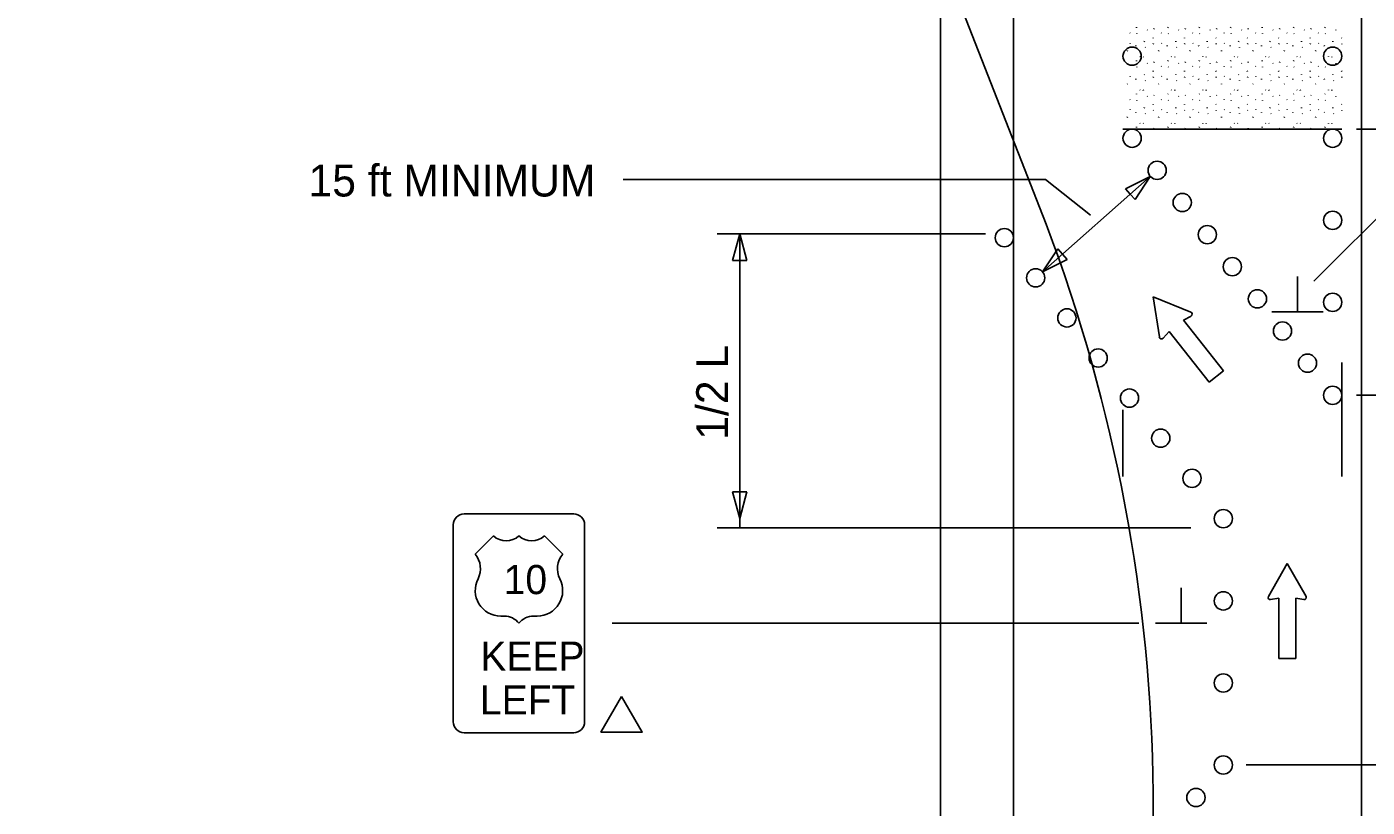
# Model space of a CAD drawing. Extents: x 16486 to 19505, y 5576 to 6998.
# Drawn here: x 16688.1 to 16981.9, y 6297.8 to 6469 of the extents above; entities that cross this region are included whole.
import ezdxf

# ---------------------------------------------------------------- set-up
doc = ezdxf.new("R2010")
doc.units = 0
for name, color, linetype in [('ALI_LEGAL_EX', 7, 'Continuous'), ('MT_SCRATCH_LEVEL_A', 7, 'Continuous'), ('MT_SCRATCH_LEVEL_E', 7, 'Continuous'), ('PAVT_EDGE_EX', 7, 'Continuous'), ('TRAFFIC_SIGNS_PR', 7, 'Continuous'), ('TYPICAL_EX', 7, 'Continuous'), ('TYPICAL_TEXT_DIMEN_PR', 7, 'Continuous')]:
    doc.layers.add(name, color=color, linetype=linetype)

msp = doc.modelspace()

# ---------------------------------------------------------------- linework, layer by layer
at = {"layer": 'ALI_LEGAL_EX'}
for p, q in [((16688.08, 6997.81), (16910.11, 6429.44)), ((16980.68, 6974.12), (16980.68, 6155.98)), ((16980.68, 6922.21), (16980.68, 6058.3))]:
    msp.add_line(p, q, dxfattribs=at)
for points in [[(16976.4, 6370.33), (16976.4, 6395.33)], [(16928.4, 6370.33), (16928.4, 6384.97)]]:
    msp.add_lwpolyline(points, dxfattribs=at)
msp.add_arc((16571.06, 6296.99), 364, 341.1474, 21.3382, dxfattribs=at)
at = {"layer": 'MT_SCRATCH_LEVEL_A'}
for p, q in [((16931.35, 6468.75), (16931.4, 6468.87)), ((16933.72, 6468.3), (16933.77, 6468.23)), ((16935.17, 6468.45), (16935.22, 6468.57)), ((16938.24, 6468.75), (16938.29, 6468.87)), ((16940.6, 6468.3), (16940.66, 6468.23)), ((16942.05, 6468.45), (16942.1, 6468.57)), ((16945.12, 6468.75), (16945.17, 6468.87)), ((16947.49, 6468.3), (16947.54, 6468.23)), ((16948.94, 6468.45), (16948.99, 6468.57)), ((16952.01, 6468.75), (16952.06, 6468.87)), ((16954.38, 6468.3), (16954.43, 6468.23)), ((16955.83, 6468.45), (16955.88, 6468.57)), ((16958.9, 6468.75), (16958.95, 6468.87)), ((16961.27, 6468.3), (16961.32, 6468.23)), ((16962.72, 6468.45), (16962.77, 6468.57)), ((16965.78, 6468.75), (16965.84, 6468.87)), ((16968.15, 6468.3), (16968.21, 6468.23)), ((16969.6, 6468.45), (16969.65, 6468.57)), ((16972.67, 6468.75), (16972.72, 6468.87)), ((16975.04, 6468.3), (16975.09, 6468.23)), ((16929.9, 6467.62), (16929.95, 6467.55)), ((16929.95, 6465.42), (16930, 6465.34)), ((16931.43, 6467.49), (16931.48, 6467.41)), ((16933.07, 6465.7), (16933.12, 6465.81)), ((16934.99, 6466.57), (16935.05, 6466.49)), ((16935.04, 6465.16), (16935.09, 6465.28)), ((16936.78, 6467.62), (16936.84, 6467.55)), ((16936.83, 6465.42), (16936.89, 6465.34)), ((16938.31, 6467.49), (16938.37, 6467.41)), ((16939.96, 6465.7), (16940.01, 6465.81)), ((16941.88, 6466.57), (16941.93, 6466.49)), ((16941.92, 6465.16), (16941.98, 6465.28)), ((16943.67, 6467.62), (16943.72, 6467.55)), ((16943.72, 6465.42), (16943.77, 6465.34)), ((16945.2, 6467.49), (16945.25, 6467.41)), ((16946.84, 6465.7), (16946.9, 6465.81)), ((16948.77, 6466.57), (16948.82, 6466.49)), ((16948.81, 6465.16), (16948.86, 6465.28)), ((16950.56, 6467.62), (16950.61, 6467.55)), ((16950.61, 6465.42), (16950.66, 6465.34)), ((16952.09, 6467.49), (16952.14, 6467.41)), ((16953.73, 6465.7), (16953.78, 6465.81)), ((16955.66, 6466.57), (16955.71, 6466.49)), ((16955.7, 6465.16), (16955.75, 6465.28)), ((16957.45, 6467.62), (16957.5, 6467.55)), ((16957.5, 6465.42), (16957.55, 6465.34)), ((16958.98, 6467.49), (16959.03, 6467.41)), ((16960.62, 6465.7), (16960.67, 6465.81)), ((16962.54, 6466.57), (16962.6, 6466.49)), ((16962.59, 6465.16), (16962.64, 6465.28)), ((16964.33, 6467.62), (16964.39, 6467.55)), ((16964.38, 6465.42), (16964.44, 6465.34)), ((16965.87, 6467.49), (16965.92, 6467.41)), ((16967.51, 6465.7), (16967.56, 6465.81)), ((16969.43, 6466.57), (16969.48, 6466.49)), ((16969.47, 6465.16), (16969.53, 6465.28)), ((16971.22, 6467.62), (16971.27, 6467.55)), ((16971.27, 6465.42), (16971.32, 6465.34)), ((16972.75, 6467.49), (16972.8, 6467.41)), ((16974.39, 6465.7), (16974.45, 6465.81)), ((16976.32, 6466.57), (16976.37, 6466.49)), ((16976.36, 6465.16), (16976.4, 6465.25)), ((16929.33, 6463.66), (16929.38, 6463.78)), ((16931.23, 6464.84), (16931.24, 6464.72)), ((16932.11, 6462.43), (16932.16, 6462.35)), ((16932.85, 6462.4), (16932.9, 6462.32)), ((16933.26, 6464.5), (16933.31, 6464.42)), ((16936.22, 6463.66), (16936.27, 6463.78)), ((16938.12, 6464.84), (16938.13, 6464.72)), ((16939, 6462.43), (16939.05, 6462.35)), ((16939.74, 6462.4), (16939.79, 6462.32)), ((16940.15, 6464.5), (16940.2, 6464.42)), ((16943.1, 6463.66), (16943.15, 6463.78)), ((16945, 6464.84), (16945.01, 6464.72)), ((16945.89, 6462.43), (16945.94, 6462.35)), ((16946.62, 6462.4), (16946.67, 6462.32)), ((16947.03, 6464.5), (16947.08, 6464.42)), ((16949.99, 6463.66), (16950.04, 6463.78)), ((16951.89, 6464.84), (16951.9, 6464.72)), ((16952.77, 6462.43), (16952.83, 6462.35)), ((16953.51, 6462.4), (16953.56, 6462.32)), ((16953.92, 6464.5), (16953.97, 6464.42)), ((16956.88, 6463.66), (16956.93, 6463.78)), ((16958.78, 6464.84), (16958.79, 6464.72)), ((16959.66, 6462.43), (16959.71, 6462.35)), ((16960.4, 6462.4), (16960.45, 6462.32)), ((16960.81, 6464.5), (16960.86, 6464.42)), ((16963.76, 6463.66), (16963.82, 6463.78)), ((16965.67, 6464.84), (16965.68, 6464.72)), ((16966.55, 6462.43), (16966.6, 6462.35)), ((16967.29, 6462.4), (16967.34, 6462.32)), ((16967.69, 6464.5), (16967.75, 6464.42)), ((16970.65, 6463.66), (16970.7, 6463.78)), ((16972.55, 6464.84), (16972.56, 6464.72)), ((16973.44, 6462.43), (16973.49, 6462.35)), ((16974.17, 6462.4), (16974.22, 6462.32)), ((16974.58, 6464.5), (16974.63, 6464.42)), ((16931.35, 6461.47), (16931.4, 6461.58)), ((16931.43, 6460.2), (16931.48, 6460.12)), ((16933.72, 6461.02), (16933.77, 6460.94)), ((16935.17, 6461.17), (16935.22, 6461.28)), ((16936.78, 6460.34), (16936.84, 6460.26)), ((16938.24, 6461.47), (16938.29, 6461.58)), ((16938.31, 6460.2), (16938.37, 6460.12)), ((16940.6, 6461.02), (16940.66, 6460.94)), ((16942.05, 6461.17), (16942.1, 6461.28)), ((16943.67, 6460.34), (16943.72, 6460.26)), ((16945.12, 6461.47), (16945.17, 6461.58)), ((16945.2, 6460.2), (16945.25, 6460.12)), ((16947.49, 6461.02), (16947.54, 6460.94)), ((16948.94, 6461.17), (16948.99, 6461.28)), ((16950.56, 6460.34), (16950.61, 6460.26)), ((16952.01, 6461.47), (16952.06, 6461.58)), ((16952.09, 6460.2), (16952.14, 6460.12)), ((16954.38, 6461.02), (16954.43, 6460.94)), ((16955.83, 6461.17), (16955.88, 6461.28)), ((16957.45, 6460.34), (16957.5, 6460.26)), ((16958.9, 6461.47), (16958.95, 6461.58)), ((16958.98, 6460.2), (16959.03, 6460.12)), ((16961.27, 6461.02), (16961.32, 6460.94)), ((16962.72, 6461.17), (16962.77, 6461.28)), ((16964.33, 6460.34), (16964.39, 6460.26)), ((16965.78, 6461.47), (16965.84, 6461.58)), ((16965.87, 6460.2), (16965.92, 6460.12)), ((16968.15, 6461.02), (16968.21, 6460.94)), ((16969.6, 6461.17), (16969.65, 6461.28)), ((16971.22, 6460.34), (16971.27, 6460.26)), ((16972.67, 6461.47), (16972.72, 6461.58)), ((16972.75, 6460.2), (16972.8, 6460.12)), ((16975.04, 6461.02), (16975.09, 6460.94)), ((16929.33, 6456.38), (16929.38, 6456.49)), ((16929.95, 6458.13), (16930, 6458.05)), ((16931.23, 6457.56), (16931.24, 6457.44)), ((16933.07, 6458.41), (16933.12, 6458.53)), ((16933.26, 6457.21), (16933.31, 6457.13)), ((16934.99, 6459.28), (16935.05, 6459.2)), ((16935.04, 6457.88), (16935.09, 6458)), ((16936.22, 6456.38), (16936.27, 6456.49)), ((16936.83, 6458.13), (16936.89, 6458.05)), ((16938.12, 6457.56), (16938.13, 6457.44)), ((16939.96, 6458.41), (16940.01, 6458.53)), ((16940.15, 6457.21), (16940.2, 6457.13)), ((16941.88, 6459.28), (16941.93, 6459.2)), ((16941.92, 6457.88), (16941.98, 6458)), ((16943.1, 6456.38), (16943.15, 6456.49)), ((16943.72, 6458.13), (16943.77, 6458.05)), ((16945, 6457.56), (16945.01, 6457.44)), ((16946.84, 6458.41), (16946.9, 6458.53)), ((16947.03, 6457.21), (16947.08, 6457.13)), ((16948.77, 6459.28), (16948.82, 6459.2)), ((16948.81, 6457.88), (16948.86, 6458)), ((16949.99, 6456.38), (16950.04, 6456.49)), ((16950.61, 6458.13), (16950.66, 6458.05)), ((16951.89, 6457.56), (16951.9, 6457.44)), ((16953.73, 6458.41), (16953.78, 6458.53)), ((16953.92, 6457.21), (16953.97, 6457.13)), ((16955.66, 6459.28), (16955.71, 6459.2)), ((16955.7, 6457.88), (16955.75, 6458)), ((16956.88, 6456.38), (16956.93, 6456.49)), ((16957.5, 6458.13), (16957.55, 6458.05)), ((16958.78, 6457.56), (16958.79, 6457.44)), ((16960.62, 6458.41), (16960.67, 6458.53)), ((16960.81, 6457.21), (16960.86, 6457.13)), ((16962.54, 6459.28), (16962.6, 6459.2)), ((16962.59, 6457.88), (16962.64, 6458)), ((16963.76, 6456.38), (16963.82, 6456.49)), ((16964.38, 6458.13), (16964.44, 6458.05)), ((16965.67, 6457.56), (16965.68, 6457.44)), ((16967.51, 6458.41), (16967.56, 6458.53)), ((16967.69, 6457.21), (16967.75, 6457.13)), ((16969.43, 6459.28), (16969.48, 6459.2)), ((16969.47, 6457.88), (16969.53, 6458)), ((16970.65, 6456.38), (16970.7, 6456.49)), ((16971.27, 6458.13), (16971.32, 6458.05)), ((16972.55, 6457.56), (16972.56, 6457.44)), ((16974.39, 6458.41), (16974.45, 6458.53)), ((16974.58, 6457.21), (16974.63, 6457.13)), ((16976.32, 6459.28), (16976.37, 6459.2)), ((16976.36, 6457.88), (16976.4, 6457.97)), ((16931.35, 6454.18), (16931.4, 6454.3)), ((16932.11, 6455.14), (16932.16, 6455.06)), ((16932.85, 6455.11), (16932.9, 6455.03)), ((16933.72, 6453.73), (16933.77, 6453.65)), ((16935.17, 6453.88), (16935.22, 6454)), ((16938.24, 6454.18), (16938.29, 6454.3)), ((16939, 6455.14), (16939.05, 6455.06)), ((16939.74, 6455.11), (16939.79, 6455.03)), ((16940.6, 6453.73), (16940.66, 6453.65)), ((16942.05, 6453.88), (16942.1, 6454)), ((16945.12, 6454.18), (16945.17, 6454.3)), ((16945.89, 6455.14), (16945.94, 6455.06)), ((16946.62, 6455.11), (16946.67, 6455.03)), ((16947.49, 6453.73), (16947.54, 6453.65)), ((16948.94, 6453.88), (16948.99, 6454)), ((16952.01, 6454.18), (16952.06, 6454.3)), ((16952.77, 6455.14), (16952.83, 6455.06)), ((16953.51, 6455.11), (16953.56, 6455.03)), ((16954.38, 6453.73), (16954.43, 6453.65)), ((16955.83, 6453.88), (16955.88, 6454)), ((16958.9, 6454.18), (16958.95, 6454.3)), ((16959.66, 6455.14), (16959.71, 6455.06)), ((16960.4, 6455.11), (16960.45, 6455.03)), ((16961.27, 6453.73), (16961.32, 6453.65)), ((16962.72, 6453.88), (16962.77, 6454)), ((16965.78, 6454.18), (16965.84, 6454.3)), ((16966.55, 6455.14), (16966.6, 6455.06)), ((16967.29, 6455.11), (16967.34, 6455.03)), ((16968.15, 6453.73), (16968.21, 6453.65)), ((16969.6, 6453.88), (16969.65, 6454)), ((16972.67, 6454.18), (16972.72, 6454.3)), ((16973.44, 6455.14), (16973.49, 6455.06)), ((16974.17, 6455.11), (16974.22, 6455.03)), ((16975.04, 6453.73), (16975.09, 6453.65)), ((16929.9, 6453.06), (16929.95, 6452.98)), ((16929.95, 6450.85), (16930, 6450.77)), ((16931.43, 6452.91), (16931.48, 6452.84)), ((16933.07, 6451.13), (16933.12, 6451.24)), ((16934.99, 6452), (16935.05, 6451.92)), ((16935.04, 6450.6), (16935.09, 6450.71)), ((16936.78, 6453.06), (16936.84, 6452.98)), ((16936.83, 6450.85), (16936.89, 6450.77)), ((16938.31, 6452.91), (16938.37, 6452.84)), ((16939.96, 6451.13), (16940.01, 6451.24)), ((16941.88, 6452), (16941.93, 6451.92)), ((16941.92, 6450.6), (16941.98, 6450.71)), ((16943.67, 6453.06), (16943.72, 6452.98)), ((16943.72, 6450.85), (16943.77, 6450.77)), ((16945.2, 6452.91), (16945.25, 6452.84)), ((16946.84, 6451.13), (16946.9, 6451.24)), ((16948.77, 6452), (16948.82, 6451.92)), ((16948.81, 6450.6), (16948.86, 6450.71)), ((16950.56, 6453.06), (16950.61, 6452.98)), ((16950.61, 6450.85), (16950.66, 6450.77)), ((16952.09, 6452.91), (16952.14, 6452.84)), ((16953.73, 6451.13), (16953.78, 6451.24)), ((16955.66, 6452), (16955.71, 6451.92)), ((16955.7, 6450.6), (16955.75, 6450.71)), ((16957.45, 6453.06), (16957.5, 6452.98)), ((16957.5, 6450.85), (16957.55, 6450.77)), ((16958.98, 6452.91), (16959.03, 6452.84)), ((16960.62, 6451.13), (16960.67, 6451.24)), ((16962.54, 6452), (16962.6, 6451.92)), ((16962.59, 6450.6), (16962.64, 6450.71)), ((16964.33, 6453.06), (16964.39, 6452.98)), ((16964.38, 6450.85), (16964.44, 6450.77)), ((16965.87, 6452.91), (16965.92, 6452.84)), ((16967.51, 6451.13), (16967.56, 6451.24)), ((16969.43, 6452), (16969.48, 6451.92)), ((16969.47, 6450.6), (16969.53, 6450.71)), ((16971.22, 6453.06), (16971.27, 6452.98)), ((16971.27, 6450.85), (16971.32, 6450.77)), ((16972.75, 6452.91), (16972.8, 6452.84)), ((16974.39, 6451.13), (16974.45, 6451.24)), ((16976.32, 6452), (16976.37, 6451.92)), ((16976.36, 6450.6), (16976.4, 6450.68)), ((16929.33, 6449.09), (16929.38, 6449.21)), ((16931.23, 6450.27), (16931.24, 6450.15)), ((16932.11, 6447.86), (16932.16, 6447.78)), ((16932.85, 6447.83), (16932.9, 6447.75)), ((16933.26, 6449.93), (16933.31, 6449.85)), ((16936.22, 6449.09), (16936.27, 6449.21)), ((16938.12, 6450.27), (16938.13, 6450.15)), ((16939, 6447.86), (16939.05, 6447.78)), ((16939.74, 6447.83), (16939.79, 6447.75)), ((16940.15, 6449.93), (16940.2, 6449.85)), ((16943.1, 6449.09), (16943.15, 6449.21)), ((16945, 6450.27), (16945.01, 6450.15)), ((16945.89, 6447.86), (16945.94, 6447.78)), ((16946.62, 6447.83), (16946.67, 6447.75)), ((16947.03, 6449.93), (16947.08, 6449.85)), ((16949.99, 6449.09), (16950.04, 6449.21)), ((16951.89, 6450.27), (16951.9, 6450.15)), ((16952.77, 6447.86), (16952.83, 6447.78)), ((16953.51, 6447.83), (16953.56, 6447.75)), ((16953.92, 6449.93), (16953.97, 6449.85)), ((16956.88, 6449.09), (16956.93, 6449.21)), ((16958.78, 6450.27), (16958.79, 6450.15)), ((16959.66, 6447.86), (16959.71, 6447.78)), ((16960.4, 6447.83), (16960.45, 6447.75)), ((16960.81, 6449.93), (16960.86, 6449.85)), ((16963.76, 6449.09), (16963.82, 6449.21)), ((16965.67, 6450.27), (16965.68, 6450.15)), ((16966.55, 6447.86), (16966.6, 6447.78)), ((16967.29, 6447.83), (16967.34, 6447.75)), ((16967.69, 6449.93), (16967.75, 6449.85)), ((16970.65, 6449.09), (16970.7, 6449.21)), ((16972.55, 6450.27), (16972.56, 6450.15)), ((16973.44, 6447.86), (16973.49, 6447.78)), ((16974.17, 6447.83), (16974.22, 6447.75)), ((16974.58, 6449.93), (16974.63, 6449.85)), ((16976.4, 6446.53), (16928.4, 6446.53)), ((16928.4, 6446.53), (16976.4, 6446.53)), ((16931.35, 6446.9), (16931.4, 6447.01)), ((16935.17, 6446.6), (16935.22, 6446.72)), ((16938.24, 6446.9), (16938.29, 6447.01)), ((16942.05, 6446.6), (16942.1, 6446.72)), ((16945.12, 6446.9), (16945.17, 6447.01)), ((16948.94, 6446.6), (16948.99, 6446.72)), ((16952.01, 6446.9), (16952.06, 6447.01)), ((16955.83, 6446.6), (16955.88, 6446.72)), ((16958.9, 6446.9), (16958.95, 6447.01)), ((16962.72, 6446.6), (16962.77, 6446.72)), ((16965.78, 6446.9), (16965.84, 6447.01)), ((16969.6, 6446.6), (16969.65, 6446.72)), ((16972.67, 6446.9), (16972.72, 6447.01))]:
    msp.add_line(p, q, dxfattribs=at)
at = {"layer": 'MT_SCRATCH_LEVEL_E'}
for p, q in [((16964.4, 6351.23), (16960.29, 6343.99)), ((16968.55, 6343.99), (16964.4, 6351.23)), ((16960.77, 6343.31), (16962.55, 6343.62)), ((16962.55, 6343.62), (16962.55, 6330.36)), ((16966.29, 6330.36), (16966.29, 6343.62)), ((16966.29, 6343.62), (16968.07, 6343.31)), ((16962.55, 6330.36), (16966.29, 6330.36))]:
    msp.add_line(p, q, dxfattribs=at)
for centre, start, end in [((16960.7, 6343.76), 150.4248, 279.9638), ((16968.14, 6343.76), 260.0362, 29.7731)]:
    msp.add_arc(centre, 0.463, start, end, dxfattribs=at)
at = {"layer": 'PAVT_EDGE_EX'}
for p, q in [((16888.4, 6480.53), (16888.4, 6125.9)), ((16904.4, 6480.53), (16904.4, 6125.9))]:
    msp.add_line(p, q, dxfattribs=at)
at = {"layer": 'TRAFFIC_SIGNS_PR'}
for p, q in [((16781.58, 6359.71), (16781.58, 6316.51)), ((16807.98, 6362.11), (16783.98, 6362.11)), ((16810.38, 6316.51), (16810.38, 6359.71)), ((16783.98, 6314.11), (16807.98, 6314.11))]:
    msp.add_line(p, q, dxfattribs=at)
for centre in [(16930.41, 6462.53), (16974.39, 6462.53), (16930.41, 6444.53), (16930.41, 6444.53), (16974.39, 6444.53), (16935.9, 6437.48), (16941.4, 6430.43), (16974.39, 6426.53), (16902.4, 6422.7), (16946.89, 6423.38), (16952.39, 6416.34), (16909.26, 6413.9), (16957.88, 6409.29), (16974.39, 6408.53), (16916.11, 6405.11), (16963.38, 6402.24), (16922.97, 6396.31), (16968.87, 6395.19), (16929.83, 6387.52), (16974.37, 6388.14), (16936.69, 6378.72), (16943.54, 6369.93), (16950.4, 6361.08), (16950.4, 6343.03), (16950.4, 6325.03), (16950.4, 6307.03), (16950.4, 6307.03), (16944.4, 6299.89)]:
    msp.add_circle(centre, 2, dxfattribs=at)
for centre, start, end in [((16783.97, 6359.71), 90, 180), ((16807.97, 6359.71), 0, 90), ((16783.97, 6316.51), 180, 270), ((16807.97, 6316.51), 270, 0)]:
    msp.add_arc(centre, 2.4, start, end, dxfattribs=at)
at = {"layer": 'TYPICAL_EX'}
for p, q in [((16786.38, 6353.31), (16790.38, 6357.31)), ((16805.58, 6353.31), (16801.58, 6357.31)), ((16791.97, 6339.7), (16792.77, 6339.7)), ((16799.98, 6339.7), (16799.18, 6339.7))]:
    msp.add_line(p, q, dxfattribs=at)
for centre, radius, start, end in [((16793.18, 6360.22), 4.04, 226.1404, 313.8596), ((16798.77, 6360.22), 4.04, 226.1404, 313.8596), ((16782.58, 6350.11), 4.96, 333.0977, 40.1936), ((16809.37, 6350.11), 4.96, 139.8064, 206.9023), ((16791.98, 6345.29), 5.59, 152.6698, 269.9013), ((16799.97, 6345.29), 5.59, 270.0987, 27.3302), ((16792.78, 6335.69), 4.01, 37.1038, 90.1385), ((16799.17, 6335.69), 4.01, 89.8615, 142.8962)]:
    msp.add_arc(centre, radius, start, end, dxfattribs=at)
at = {"layer": 'TYPICAL_TEXT_DIMEN_PR'}
for p, q in [((16979.6, 6446.53), (17065.4, 6446.53)), ((16934.4, 6436.16), (16910.76, 6415.23)), ((16928.97, 6433.45), (16934.4, 6436.16)), ((16934.4, 6436.16), (16931.06, 6431.1)), ((16970.24, 6413.2), (16993.65, 6436.53)), ((16818.83, 6435.45), (16911.45, 6435.45)), ((16921.31, 6427.65), (16911.45, 6435.45)), ((16930.01, 6432.27), (16928.97, 6433.45)), ((16931.06, 6431.1), (16930.01, 6432.27)), ((16839.4, 6423.59), (16898.3, 6423.59)), ((16842.83, 6417.73), (16844.4, 6423.59)), ((16844.4, 6423.59), (16844.4, 6359.08)), ((16844.4, 6423.59), (16845.97, 6417.73)), ((16910.76, 6415.23), (16914.1, 6420.29)), ((16914.1, 6420.29), (16915.15, 6419.11)), ((16915.15, 6419.11), (16916.19, 6417.94)), ((16844.4, 6417.73), (16842.83, 6417.73)), ((16845.97, 6417.73), (16844.4, 6417.73)), ((16916.19, 6417.94), (16910.76, 6415.23)), ((16966.68, 6406.41), (16966.68, 6414.19)), ((16943.28, 6406.4), (16935.01, 6409.7)), ((16935.01, 6409.7), (16936.38, 6400.93)), ((16941.64, 6404.6), (16943.33, 6405.51)), ((16950.42, 6393.52), (16941.64, 6404.6)), ((16972.3, 6406.41), (16961.05, 6406.41)), ((16937.23, 6400.68), (16938.51, 6402.12)), ((16938.51, 6402.12), (16947.3, 6391.04)), ((16947.3, 6391.04), (16950.42, 6393.52)), ((17095.19, 6388.14), (16979.6, 6388.14)), ((16844.4, 6361.08), (16842.83, 6366.94)), ((16842.83, 6366.94), (16844.4, 6366.94)), ((16844.4, 6366.94), (16845.97, 6366.94)), ((16845.97, 6366.94), (16844.4, 6361.08)), ((16943.29, 6359.08), (16839.4, 6359.08)), ((16941.15, 6338.14), (16941.15, 6345.93)), ((16816.43, 6338.14), (16931.9, 6338.14)), ((16946.78, 6338.14), (16935.53, 6338.14)), ((16955.45, 6307.03), (17095.19, 6307.03))]:
    msp.add_line(p, q, dxfattribs=at)
msp.add_lwpolyline([(16818.47, 6322.07), (16813.95, 6314.24), (16823, 6314.24)], close=True, dxfattribs=at)
for centre, start, end in [((16943.08, 6405.94), 298.4553, 68.1923), ((16936.86, 6401.01), 188.844, 318.3829)]:
    msp.add_arc(centre, 0.494, start, end, dxfattribs=at)

# ---------------------------------------------------------------- texts
at = {"layer": 'TRAFFIC_SIGNS_PR'}
for s, p in [('10', (16792.63, 6344.51)), ('KEEP', (16787.51, 6327.71)), ('LEFT', (16787.42, 6318.11))]:
    msp.add_text(s, height=6.4, dxfattribs=at).set_placement(p)
at = {"layer": 'TYPICAL_TEXT_DIMEN_PR'}
msp.add_text('15 ft MINIMUM', height=7, dxfattribs=at).set_placement((16749.83, 6431.75))
msp.add_text('1/2 L', height=7, rotation=90, dxfattribs=at).set_placement((16841.84, 6378.38))

doc.saveas('drawing.dxf')
